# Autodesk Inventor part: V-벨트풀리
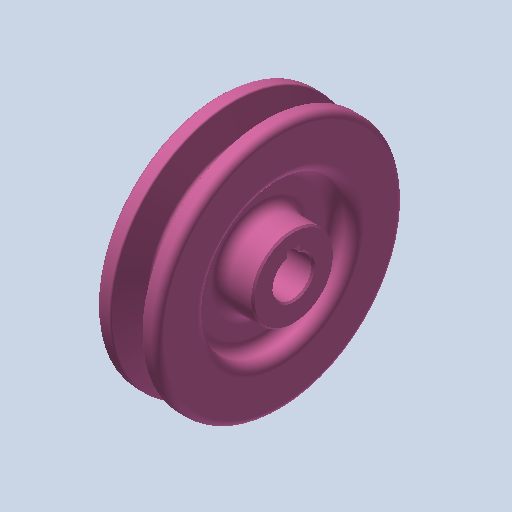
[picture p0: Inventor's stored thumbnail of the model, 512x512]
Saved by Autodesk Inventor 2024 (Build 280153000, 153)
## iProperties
Created: 2015-11
Part Number: V-벨트풀리
Material: 강철, 탄소
Document SubType Name: Modeling
Designer: mduedu
Density: 1 g/cm^3
Appearance: 분홍색
Author: mduedu
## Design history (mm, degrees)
revolve "회전1" stored, may be unused: angle "d8" = 90 deg
sketch "스케치2"
  geometry: C1 r 22.5 at (0, 0); C2 r 12.5 at (0, 0); C3 r 37.7 at (0, 0) reference; 1 further point
  constraints: 2 centre point, 2 coincident
  dimensions: "d35" = 15.2 radial gap between concentric circles of C3 C1 (computed from d5); "d36" = 10 radial gap between concentric circles of C1 C2
extrude "돌출1" cut sketch "스케치2" distance "d11" = 6; taper "d12" = 0 deg
fillet "모깎기1" dims "d13" = 3
feature "면 이동1"
fillet "모깎기2" dims "d14" = 3
fillet "모깎기3" dims "d15" = 1, "d16" = 0.5, "d17" = 2
hole "구멍1" diameter "d20" = 12; stored, may be unused: countersink angle "d24" = 90 deg, drill point angle "d26" = 118 deg; dims "d21" = 6, "d22" = 4, "d23" = 2, "d25" = 8, "d37" = 10, "d38" = 10
sketch "스케치3"
  geometry: L1 (-2, 0)-(2, 0); L2 (2, 0)-(2, 7.8); L3 (2, 7.8)-(-2, 7.8); L4 (-2, 7.8)-(-2, 0); C1 r 12.5 at (0, 0) reference; 2 further points
  constraints: 8 end point, 2 coincident, 2 parallel, 1 horizontal, 1 midpoint, 1 perpendicular
  dimensions: "d27" = 4 distance of L2.end L3.end; "d29" = 7.8 distance of L3.end L1.start
extrude "돌출2" cut sketch "스케치3" extent not by distance; stored distance "d30" = 6; taper "d31" = 0 deg
chamfer "모따기1" distance "d32" = 0.5; stored, may be unused: second distance "d33" = 2, angle "d34" = 45 deg
node "솔리드1"
mirror "대칭1"
sketch "스케치1"
  geometry: L1 (-9.5, 0)-(9.5, 0); L2 (0, 0)-(0, 37.7); L3 (-4.825, 37.7)-(-9.5, 37.7); L4 (-9.5, 37.7)-(-9.5, 0); L5 (0, 28.7)-(-2.074, 28.7); L6 (-2.074, 28.7)-(-4.825, 37.7); L7 (4.825, 37.7)-(9.5, 37.7); L8 (9.5, 37.7)-(9.5, 0); L9 (0, 28.7)-(2.074, 28.7); L10 (2.074, 28.7)-(4.825, 37.7); L11 (-9.5, 35)-(9.5, 35); 3 further points
  constraints: 22 end point, 7 point on line, 4 perpendicular, 3 symmetric about line, 1 coincident, 1 horizontal, 1 horizontal alignment, 1 midpoint, 1 vertical
  dimensions: "d0" = 19 distance of L1.start L1.end; "d2" = 75.4 diameter of L2.end L1 (derived); "d3" = 34 deg angle of L10 L6; "d4" = 6.3 distance between parallel lines of L11 L9; "d5" = 2.7 distance between parallel lines of L7 L11; "d6" = 8 distance of point (4, 35) point (-4, 35); "d7" = 70 diameter of L11 L1
